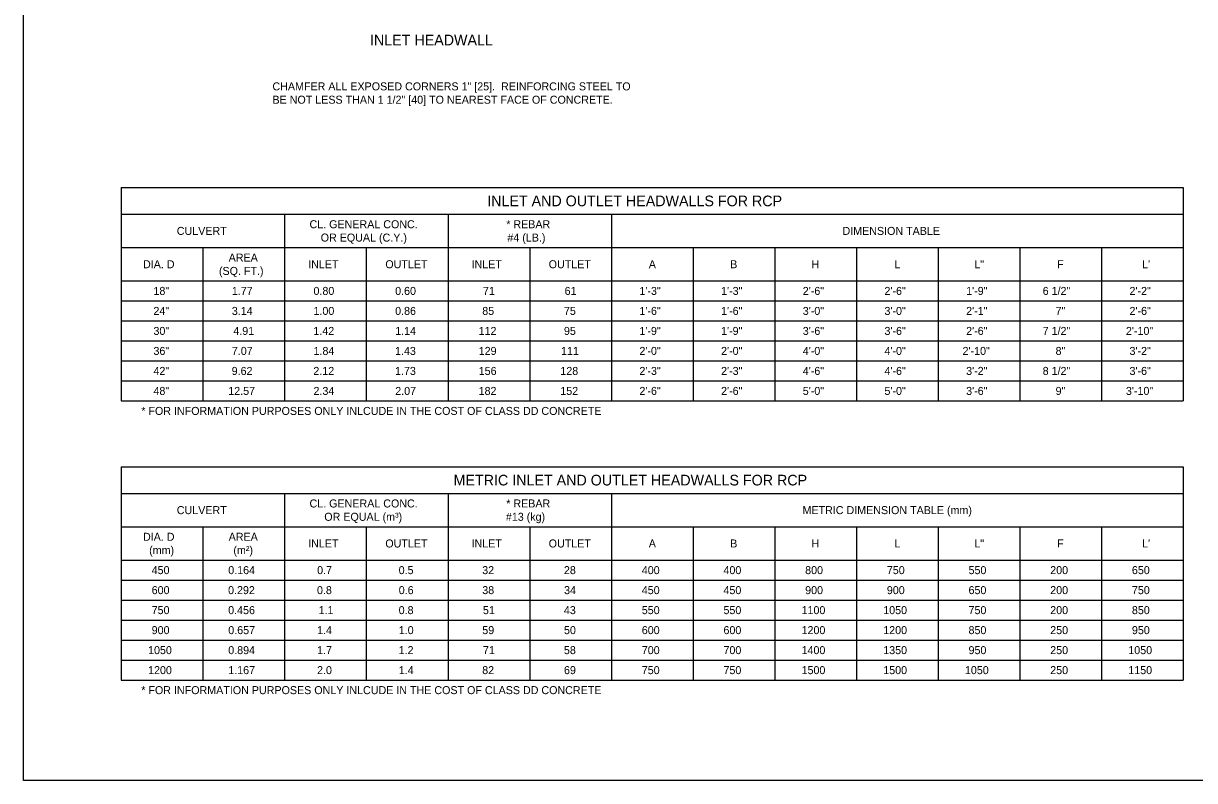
# Model space of a CAD drawing. Extents: x 49991.4 to 50021, y 49987.6 to 50011.4.
# Drawn here: x 49999.38 to 50008.17, y 49987.8 to 49993.48 of the extents above; entities that cross this region are included whole.
import ezdxf

# ---------------------------------------------------------------- set-up
doc = ezdxf.new("R2010")
doc.units = 0
doc.layers.add('Level 1', color=7, linetype='Continuous')
doc.layers.add('Level 2', color=7, linetype='Continuous')

msp = doc.modelspace()

# ---------------------------------------------------------------- linework, layer by layer
at = {"layer": 'Level 1'}
msp.add_lwpolyline([(49999.3835, 49998.9992), (50016.7501, 49998.9992), (50016.7501, 49987.7988), (49999.3835, 49987.7988)], close=True, dxfattribs=at)
at = {"layer": 'Level 2'}
for p, q in [((50000.1171, 49992.2461), (50000.1171, 49990.6461)), ((50000.1171, 49992.2461), (50008.0796, 49992.2461)), ((50008.0796, 49992.2461), (50008.0796, 49990.6461)), ((50000.1171, 49992.0461), (50008.0796, 49992.0461)), ((50001.3421, 49992.0461), (50001.3421, 49990.6461)), ((50002.5671, 49992.0461), (50002.5671, 49990.6461)), ((50003.7921, 49992.0461), (50003.7921, 49990.6461)), ((50000.1171, 49991.7961), (50008.0796, 49991.7961)), ((50000.7296, 49991.7961), (50000.7296, 49990.6461)), ((50001.9546, 49991.7961), (50001.9546, 49990.6461)), ((50003.1796, 49991.7961), (50003.1796, 49990.6461)), ((50004.4046, 49991.7961), (50004.4046, 49990.6461)), ((50005.0171, 49991.7961), (50005.0171, 49990.6461)), ((50005.6296, 49991.7961), (50005.6296, 49990.6461)), ((50006.2421, 49991.7961), (50006.2421, 49990.6461)), ((50006.8546, 49991.7961), (50006.8546, 49990.6461)), ((50007.4671, 49991.7961), (50007.4671, 49990.6461)), ((50000.1171, 49991.5461), (50008.0796, 49991.5461)), ((50000.1171, 49991.3961), (50008.0796, 49991.3961)), ((50000.1171, 49991.2461), (50008.0796, 49991.2461)), ((50000.1171, 49991.0961), (50008.0796, 49991.0961)), ((50000.1171, 49990.9461), (50008.0796, 49990.9461)), ((50000.1171, 49990.7961), (50008.0796, 49990.7961)), ((50000.1171, 49990.6461), (50008.0796, 49990.6461)), ((50000.1171, 49990.1521), (50000.1171, 49988.5521)), ((50000.1171, 49990.1521), (50008.0796, 49990.1521)), ((50008.0796, 49990.1521), (50008.0796, 49988.5521)), ((50000.1171, 49989.9521), (50008.0796, 49989.9521)), ((50001.3421, 49989.9521), (50001.3421, 49988.5521)), ((50002.5671, 49989.9521), (50002.5671, 49988.5521)), ((50003.7921, 49989.9521), (50003.7921, 49988.5521)), ((50000.1171, 49989.7021), (50008.0796, 49989.7021)), ((50000.7296, 49989.7021), (50000.7296, 49988.5521)), ((50001.9546, 49989.7021), (50001.9546, 49988.5521)), ((50003.1796, 49989.7021), (50003.1796, 49988.5521)), ((50004.4046, 49989.7021), (50004.4046, 49988.5521)), ((50005.0171, 49989.7021), (50005.0171, 49988.5521)), ((50005.6296, 49989.7021), (50005.6296, 49988.5521)), ((50006.2421, 49989.7021), (50006.2421, 49988.5521)), ((50006.8546, 49989.7021), (50006.8546, 49988.5521)), ((50007.4671, 49989.7021), (50007.4671, 49988.5521)), ((50000.1171, 49989.4521), (50008.0796, 49989.4521)), ((50000.1171, 49989.3021), (50008.0796, 49989.3021)), ((50000.1171, 49989.1521), (50008.0796, 49989.1521)), ((50000.1171, 49989.0021), (50008.0796, 49989.0021)), ((50000.1171, 49988.8521), (50008.0796, 49988.8521)), ((50000.1171, 49988.7021), (50008.0796, 49988.7021)), ((50000.1171, 49988.5521), (50008.0796, 49988.5521))]:
    msp.add_line(p, q, dxfattribs=at)

# ---------------------------------------------------------------- texts
for s, height, p in [('INLET HEADWALL', 0.08, (50001.9821, 49993.3128)), ('CHAMFER ALL EXPOSED CORNERS 1" [25].  REINFORCING STEEL TO', 0.06, (50001.2508, 49992.9751)), ('BE NOT LESS THAN 1 1/2" [40] TO NEAREST FACE OF CONCRETE.', 0.06, (50001.2508, 49992.8751)), ('INLET AND OUTLET HEADWALLS FOR RCP', 0.08, (50002.861, 49992.1061)), ('CULVERT', 0.06, (50000.5336, 49991.8911)), ('CL. GENERAL CONC.', 0.06, (50001.5288, 49991.9411)), ('* REBAR', 0.06, (50003.004, 49991.9411)), ('DIMENSION TABLE', 0.06, (50005.5251, 49991.8911)), ('OR EQUAL (C.Y.)', 0.06, (50001.6127, 49991.8411)), ('#4 (LB.)', 0.06, (50003.0125, 49991.8411)), ('DIA. D', 0.06, (50000.2802, 49991.6411)), ('AREA', 0.06, (50000.9226, 49991.6911)), ('INLET', 0.06, (50001.5188, 49991.6411)), ('OUTLET', 0.06, (50002.0971, 49991.6411)), ('INLET', 0.06, (50002.7438, 49991.6411)), ('OUTLET', 0.06, (50003.3221, 49991.6411)), ('A', 0.06, (50004.0726, 49991.6411)), ('B', 0.06, (50004.6832, 49991.6411)), ('H', 0.06, (50005.2914, 49991.6411)), ('L', 0.06, (50005.9147, 49991.6411)), ('L"', 0.06, (50006.5136, 49991.6411)), ('F', 0.06, (50007.1347, 49991.6411)), ("L'", 0.06, (50007.7717, 49991.6411)), ('(SQ. FT.)', 0.06, (50000.8496, 49991.5911)), ('18"', 0.06, (50000.3585, 49991.4411)), ('1.77', 0.06, (50000.9464, 49991.4411)), ('0.80', 0.06, (50001.5584, 49991.4411)), ('0.60', 0.06, (50002.1709, 49991.4411)), ('71', 0.06, (50002.8291, 49991.4411)), ('61', 0.06, (50003.4416, 49991.4411)), ('1\'-3"', 0.06, (50004.0023, 49991.4411)), ('1\'-3"', 0.06, (50004.6148, 49991.4411)), ('2\'-6"', 0.06, (50005.2273, 49991.4411)), ('2\'-6"', 0.06, (50005.8398, 49991.4411)), ('1\'-9"', 0.06, (50006.4523, 49991.4411)), ('6 1/2"', 0.06, (50007.0262, 49991.4411)), ('2\'-2"', 0.06, (50007.6773, 49991.4411)), ('24"', 0.06, (50000.3585, 49991.2911)), ('3.14', 0.06, (50000.9462, 49991.2911)), ('1.00', 0.06, (50001.5584, 49991.2911)), ('0.86', 0.06, (50002.1707, 49991.2911)), ('85', 0.06, (50002.8239, 49991.2911)), ('75', 0.06, (50003.4364, 49991.2911)), ('1\'-6"', 0.06, (50004.0023, 49991.2911)), ('1\'-6"', 0.06, (50004.6148, 49991.2911)), ('3\'-0"', 0.06, (50005.2273, 49991.2911)), ('3\'-0"', 0.06, (50005.8398, 49991.2911)), ('2\'-1"', 0.06, (50006.4523, 49991.2911)), ('7"', 0.06, (50007.1229, 49991.2911)), ('2\'-6"', 0.06, (50007.6773, 49991.2911)), ('30"', 0.06, (50000.3585, 49991.1411)), ('4.91', 0.06, (50000.9573, 49991.1411)), ('1.42', 0.06, (50001.5575, 49991.1411)), ('1.14', 0.06, (50002.1712, 49991.1411)), ('112', 0.06, (50002.7967, 49991.1411)), ('95', 0.06, (50003.4364, 49991.1411)), ('1\'-9"', 0.06, (50004.0023, 49991.1411)), ('1\'-9"', 0.06, (50004.6148, 49991.1411)), ('3\'-6"', 0.06, (50005.2273, 49991.1411)), ('3\'-6"', 0.06, (50005.8398, 49991.1411)), ('2\'-6"', 0.06, (50006.4523, 49991.1411)), ('7 1/2"', 0.06, (50007.0262, 49991.1411)), ('2\'-10"', 0.06, (50007.6504, 49991.1411)), ('36"', 0.06, (50000.3585, 49990.9911)), ('7.07', 0.06, (50000.9464, 49990.9911)), ('1.84', 0.06, (50001.5587, 49990.9911)), ('1.43', 0.06, (50002.17, 49990.9911)), ('129', 0.06, (50002.7974, 49990.9911)), ('111', 0.06, (50003.4146, 49990.9911)), ('2\'-0"', 0.06, (50004.0023, 49990.9911)), ('2\'-0"', 0.06, (50004.6148, 49990.9911)), ('4\'-0"', 0.06, (50005.2273, 49990.9911)), ('4\'-0"', 0.06, (50005.8398, 49990.9911)), ('2\'-10"', 0.06, (50006.4254, 49990.9911)), ('8"', 0.06, (50007.1229, 49990.9911)), ('3\'-2"', 0.06, (50007.6773, 49990.9911)), ('42"', 0.06, (50000.3585, 49990.8411)), ('9.62', 0.06, (50000.945, 49990.8411)), ('2.12', 0.06, (50001.5575, 49990.8411)), ('1.73', 0.06, (50002.17, 49990.8411)), ('156', 0.06, (50002.7974, 49990.8411)), ('128', 0.06, (50003.4094, 49990.8411)), ('2\'-3"', 0.06, (50004.0023, 49990.8411)), ('2\'-3"', 0.06, (50004.6148, 49990.8411)), ('4\'-6"', 0.06, (50005.2273, 49990.8411)), ('4\'-6"', 0.06, (50005.8398, 49990.8411)), ('3\'-2"', 0.06, (50006.4523, 49990.8411)), ('8 1/2"', 0.06, (50007.0262, 49990.8411)), ('3\'-6"', 0.06, (50007.6773, 49990.8411)), ('48"', 0.06, (50000.3585, 49990.6911)), ('12.57', 0.06, (50000.9195, 49990.6911)), ('2.34', 0.06, (50001.5587, 49990.6911)), ('2.07', 0.06, (50002.1714, 49990.6911)), ('182', 0.06, (50002.7967, 49990.6911)), ('152', 0.06, (50003.4092, 49990.6911)), ('2\'-6"', 0.06, (50004.0023, 49990.6911)), ('2\'-6"', 0.06, (50004.6148, 49990.6911)), ('5\'-0"', 0.06, (50005.2273, 49990.6911)), ('5\'-0"', 0.06, (50005.8398, 49990.6911)), ('3\'-6"', 0.06, (50006.4523, 49990.6911)), ('9"', 0.06, (50007.1229, 49990.6911)), ('3\'-10"', 0.06, (50007.6504, 49990.6911)), ('* FOR INFORMATION PURPOSES ONLY INLCUDE IN THE COST OF CLASS DD CONCRETE', 0.06, (50000.2672, 49990.5411)), ('METRIC INLET AND OUTLET HEADWALLS FOR RCP', 0.08, (50002.609, 49990.0121)), ('CULVERT', 0.06, (50000.5336, 49989.7971)), ('CL. GENERAL CONC.', 0.06, (50001.5288, 49989.8471)), ('* REBAR', 0.06, (50003.004, 49989.8471)), ('METRIC DIMENSION TABLE (mm)', 0.06, (50005.2252, 49989.7971)), ('OR EQUAL (m³)', 0.06, (50001.6396, 49989.7471)), ('#13 (kg)', 0.06, (50003.001, 49989.7471)), ('DIA. D', 0.06, (50000.2802, 49989.5971)), ('AREA', 0.06, (50000.9226, 49989.5971)), ('INLET', 0.06, (50001.5188, 49989.5471)), ('OUTLET', 0.06, (50002.0971, 49989.5471)), ('INLET', 0.06, (50002.7438, 49989.5471)), ('OUTLET', 0.06, (50003.3221, 49989.5471)), ('A', 0.06, (50004.0726, 49989.5471)), ('B', 0.06, (50004.6832, 49989.5471)), ('H', 0.06, (50005.2914, 49989.5471)), ('L', 0.06, (50005.9147, 49989.5471)), ('L"', 0.06, (50006.5136, 49989.5471)), ('F', 0.06, (50007.1347, 49989.5471)), ("L'", 0.06, (50007.7717, 49989.5471)), ('(mm)', 0.06, (50000.3263, 49989.4971)), ('(m²)', 0.06, (50000.9578, 49989.4971)), ('450', 0.06, (50000.3452, 49989.3471)), ('0.164', 0.06, (50000.9193, 49989.3471)), ('0.7', 0.06, (50001.5858, 49989.3471)), ('0.5', 0.06, (50002.1972, 49989.3471)), ('32', 0.06, (50002.8237, 49989.3471)), ('28', 0.06, (50003.4364, 49989.3471)), ('400', 0.06, (50004.0202, 49989.3471)), ('400', 0.06, (50004.6327, 49989.3471)), ('800', 0.06, (50005.2452, 49989.3471)), ('750', 0.06, (50005.8577, 49989.3471)), ('550', 0.06, (50006.4702, 49989.3471)), ('200', 0.06, (50007.0827, 49989.3471)), ('650', 0.06, (50007.6952, 49989.3471)), ('600', 0.06, (50000.3452, 49989.1971)), ('0.292', 0.06, (50000.9181, 49989.1971)), ('0.8', 0.06, (50001.5847, 49989.1971)), ('0.6', 0.06, (50002.1977, 49989.1971)), ('38', 0.06, (50002.8239, 49989.1971)), ('34', 0.06, (50003.4374, 49989.1971)), ('450', 0.06, (50004.0202, 49989.1971)), ('450', 0.06, (50004.6327, 49989.1971)), ('900', 0.06, (50005.2452, 49989.1971)), ('900', 0.06, (50005.8577, 49989.1971)), ('650', 0.06, (50006.4702, 49989.1971)), ('200', 0.06, (50007.0827, 49989.1971)), ('750', 0.06, (50007.6952, 49989.1971)), ('750', 0.06, (50000.3452, 49989.0471)), ('0.456', 0.06, (50000.9188, 49989.0471)), ('1.1', 0.06, (50001.5967, 49989.0471)), ('0.8', 0.06, (50002.1972, 49989.0471)), ('51', 0.06, (50002.8291, 49989.0471)), ('43', 0.06, (50003.4361, 49989.0471)), ('550', 0.06, (50004.0202, 49989.0471)), ('550', 0.06, (50004.6327, 49989.0471)), ('1100', 0.06, (50005.2182, 49989.0471)), ('1050', 0.06, (50005.8307, 49989.0471)), ('750', 0.06, (50006.4702, 49989.0471)), ('200', 0.06, (50007.0827, 49989.0471)), ('850', 0.06, (50007.6952, 49989.0471)), ('900', 0.06, (50000.3452, 49988.8971)), ('0.657', 0.06, (50000.9195, 49988.8971)), ('1.4', 0.06, (50001.5857, 49988.8971)), ('1.0', 0.06, (50002.1978, 49988.8971)), ('59', 0.06, (50002.8243, 49988.8971)), ('50', 0.06, (50003.4369, 49988.8971)), ('600', 0.06, (50004.0202, 49988.8971)), ('600', 0.06, (50004.6327, 49988.8971)), ('1200', 0.06, (50005.2182, 49988.8971)), ('1200', 0.06, (50005.8307, 49988.8971)), ('850', 0.06, (50006.4702, 49988.8971)), ('250', 0.06, (50007.0827, 49988.8971)), ('950', 0.06, (50007.6952, 49988.8971)), ('1050', 0.06, (50000.3182, 49988.7471)), ('0.894', 0.06, (50000.9193, 49988.7471)), ('1.7', 0.06, (50001.5858, 49988.7471)), ('1.2', 0.06, (50002.197, 49988.7471)), ('71', 0.06, (50002.8291, 49988.7471)), ('58', 0.06, (50003.4364, 49988.7471)), ('700', 0.06, (50004.0202, 49988.7471)), ('700', 0.06, (50004.6327, 49988.7471)), ('1400', 0.06, (50005.2182, 49988.7471)), ('1350', 0.06, (50005.8307, 49988.7471)), ('950', 0.06, (50006.4702, 49988.7471)), ('250', 0.06, (50007.0827, 49988.7471)), ('1050', 0.06, (50007.6682, 49988.7471)), ('1200', 0.06, (50000.3182, 49988.5971)), ('1.167', 0.06, (50000.9195, 49988.5971)), ('2.0', 0.06, (50001.5853, 49988.5971)), ('1.4', 0.06, (50002.1982, 49988.5971)), ('82', 0.06, (50002.8237, 49988.5971)), ('69', 0.06, (50003.4368, 49988.5971)), ('750', 0.06, (50004.0202, 49988.5971)), ('750', 0.06, (50004.6327, 49988.5971)), ('1500', 0.06, (50005.2182, 49988.5971)), ('1500', 0.06, (50005.8307, 49988.5971)), ('1050', 0.06, (50006.4432, 49988.5971)), ('250', 0.06, (50007.0827, 49988.5971)), ('1150', 0.06, (50007.6682, 49988.5971)), ('* FOR INFORMATION PURPOSES ONLY INLCUDE IN THE COST OF CLASS DD CONCRETE', 0.06, (50000.2672, 49988.4471))]:
    msp.add_text(s, height=height, dxfattribs=at).set_placement(p)

doc.saveas('drawing.dxf')
